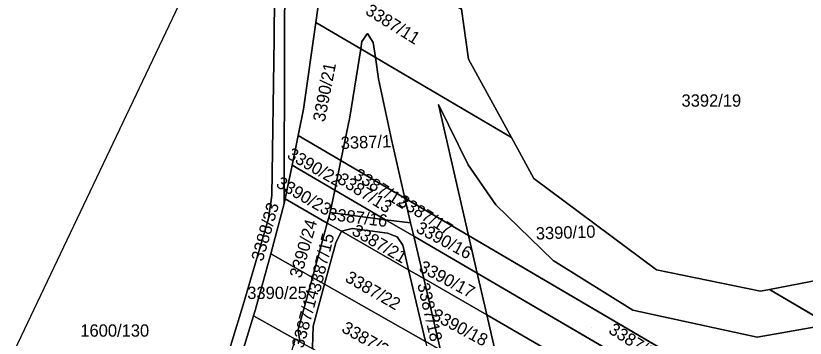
# Model space of a CAD drawing. Extents: x -262715 to -259381, y -1237238 to -1231182.
# Drawn here: x -261658.5 to -261530.6, y -1236768.1 to -1236715.8 of the extents above; entities that cross this region are included whole.
import ezdxf

# ---------------------------------------------------------------- set-up
doc = ezdxf.new("R2010")
doc.units = 0
for name, color, linetype in [('body_kn', 7, 'Continuous'), ('kladpar_druhypozemkov', 7, 'Continuous'), ('kladpar_hranice', 7, 'Continuous'), ('kladpar_parcelnecisla', 7, 'Continuous'), ('kladpar_plochy', 7, 'Continuous'), ('kladpar_sipky', 7, 'Continuous')]:
    doc.layers.add(name, color=color, linetype=linetype)

msp = doc.modelspace()

# ---------------------------------------------------------------- linework, layer by layer
at = {"layer": 'body_kn'}
for p, q in [((-261609.91, -1236716.84), (-261609.91, -1236716.84)), ((-261609.91, -1236716.84), (-261609.91, -1236716.84)), ((-261601.5, -1236718.66), (-261601.5, -1236718.66)), ((-261616.66, -1236719.48), (-261616.66, -1236719.48)), ((-261614.95, -1236719.59), (-261614.95, -1236719.59)), ((-261602.42, -1236719.93), (-261602.42, -1236719.93)), ((-261600.59, -1236720.1), (-261600.59, -1236720.1)), ((-261602.61, -1236721.14), (-261602.61, -1236721.14)), ((-261602.61, -1236721.14), (-261602.61, -1236721.14)), ((-261600.23, -1236722.54), (-261600.23, -1236722.54)), ((-261585.14, -1236722.79), (-261585.14, -1236722.79)), ((-261599.71, -1236726.01), (-261599.71, -1236726.01)), ((-261590, -1236730.13), (-261590, -1236730.13)), ((-261611.87, -1236730.89), (-261611.87, -1236730.89)), ((-261604.37, -1236732.22), (-261604.37, -1236732.22)), ((-261612.74, -1236735.16), (-261612.74, -1236735.16)), ((-261612.74, -1236735.16), (-261612.74, -1236735.16)), ((-261597.63, -1236735.85), (-261597.63, -1236735.85)), ((-261578.19, -1236735.52), (-261578.19, -1236735.52)), ((-261578.19, -1236735.52), (-261578.19, -1236735.52)), ((-261605.82, -1236739.23), (-261605.82, -1236739.23)), ((-261605.82, -1236739.23), (-261605.82, -1236739.23)), ((-261613.73, -1236740), (-261613.73, -1236740)), ((-261613.73, -1236740), (-261613.73, -1236740)), ((-261585.18, -1236739.92), (-261585.18, -1236739.92)), ((-261574.56, -1236742.18), (-261574.56, -1236742.18)), ((-261606.82, -1236744.04), (-261606.82, -1236744.04)), ((-261606.82, -1236744.04), (-261606.82, -1236744.04)), ((-261617.01, -1236744.91), (-261617.01, -1236744.91)), ((-261614.85, -1236745.47), (-261614.85, -1236745.47)), ((-261614.85, -1236745.47), (-261614.85, -1236745.47)), ((-261595.45, -1236745.32), (-261595.45, -1236745.32)), ((-261595.45, -1236745.32), (-261595.45, -1236745.32)), ((-261615, -1236746.23), (-261615, -1236746.23)), ((-261580.74, -1236746.42), (-261580.74, -1236746.42)), ((-261607.58, -1236747.69), (-261607.58, -1236747.69)), ((-261607.58, -1236747.69), (-261607.58, -1236747.69)), ((-261617.53, -1236748.67), (-261617.53, -1236748.67)), ((-261608.04, -1236749.39), (-261608.04, -1236749.39)), ((-261608.04, -1236749.39), (-261608.04, -1236749.39)), ((-261598.59, -1236748.85), (-261598.59, -1236748.85)), ((-261598.59, -1236748.85), (-261598.59, -1236748.85)), ((-261594.52, -1236749.37), (-261594.52, -1236749.37)), ((-261605.73, -1236750.68), (-261605.73, -1236750.68)), ((-261605.73, -1236750.68), (-261605.73, -1236750.68)), ((-261603.98, -1236750.28), (-261603.98, -1236750.28)), ((-261598.28, -1236751.01), (-261598.28, -1236751.01)), ((-261596.72, -1236751.59), (-261596.72, -1236751.59)), ((-261594.01, -1236751.52), (-261594.01, -1236751.52)), ((-261594.01, -1236751.52), (-261594.01, -1236751.52)), ((-261585.13, -1236751.39), (-261585.13, -1236751.39)), ((-261585.13, -1236751.39), (-261585.13, -1236751.39)), ((-261606.66, -1236752.6), (-261606.66, -1236752.6)), ((-261595.81, -1236752.95), (-261595.81, -1236752.95)), ((-261617.2, -1236754.37), (-261617.2, -1236754.37)), ((-261617.2, -1236754.37), (-261617.2, -1236754.37)), ((-261571.43, -1236755.44), (-261571.43, -1236755.44)), ((-261594.86, -1236756.98), (-261594.86, -1236756.98)), ((-261594.86, -1236756.98), (-261594.86, -1236756.98)), ((-261583.73, -1236757.53), (-261583.73, -1236757.53)), ((-261583.73, -1236757.53), (-261583.73, -1236757.53)), ((-261554.67, -1236756.97), (-261554.67, -1236756.97)), ((-261610.45, -1236758.21), (-261610.45, -1236758.21)), ((-261610.45, -1236758.21), (-261610.45, -1236758.21)), ((-261592.4, -1236758.4), (-261592.4, -1236758.4)), ((-261592.4, -1236758.4), (-261592.4, -1236758.4)), ((-261608.49, -1236759.32), (-261608.49, -1236759.32)), ((-261608.49, -1236759.32), (-261608.49, -1236759.32)), ((-261536.36, -1236760.16), (-261536.36, -1236760.16)), ((-261536.36, -1236760.16), (-261536.36, -1236760.16)), ((-261537.81, -1236760.44), (-261537.81, -1236760.44)), ((-261621.67, -1236762.66), (-261621.67, -1236762.66)), ((-261619.69, -1236763.54), (-261619.69, -1236763.54)), ((-261558.51, -1236763.51), (-261558.51, -1236763.51)), ((-261619.97, -1236764.44), (-261619.97, -1236764.44)), ((-261619.97, -1236764.44), (-261619.97, -1236764.44)), ((-261582.18, -1236764.28), (-261582.18, -1236764.28)), ((-261582.18, -1236764.28), (-261582.18, -1236764.28)), ((-261610.33, -1236766.1), (-261610.33, -1236766.1)), ((-261612.74, -1236766.62), (-261612.74, -1236766.62)), ((-261538.34, -1236767.9), (-261538.34, -1236767.9))]:
    msp.add_line(p, q, dxfattribs=at)
at = {"layer": 'kladpar_druhypozemkov'}
for p, q in [((-261601.43, -1236721.27), (-261601.43, -1236721.27)), ((-261609.78, -1236726.54), (-261609.78, -1236726.54)), ((-261545.72, -1236728.04), (-261545.72, -1236728.04)), ((-261601.45, -1236734.83), (-261601.45, -1236734.83)), ((-261609.61, -1236739.69), (-261609.61, -1236739.69)), ((-261604.85, -1236741.85), (-261604.85, -1236741.85)), ((-261615.92, -1236743.88), (-261615.92, -1236743.88)), ((-261610.5, -1236744.77), (-261610.5, -1236744.77)), ((-261604.29, -1236747.74), (-261604.29, -1236747.74)), ((-261595.5, -1236750.62), (-261595.5, -1236750.62)), ((-261569.59, -1236750.25), (-261569.59, -1236750.25)), ((-261612.88, -1236752.22), (-261612.88, -1236752.22)), ((-261607.4, -1236751.83), (-261607.4, -1236751.83)), ((-261588.52, -1236751.75), (-261588.52, -1236751.75)), ((-261598.18, -1236752.66), (-261598.18, -1236752.66)), ((-261594.55, -1236754.58), (-261594.55, -1236754.58)), ((-261587.96, -1236758.17), (-261587.96, -1236758.17)), ((-261614.96, -1236759.73), (-261614.96, -1236759.73)), ((-261599.79, -1236760.04), (-261599.79, -1236760.04)), ((-261593.52, -1236760), (-261593.52, -1236760)), ((-261609.86, -1236760.62), (-261609.86, -1236760.62)), ((-261642.3, -1236765.79), (-261642.3, -1236765.79)), ((-261585.91, -1236766.13), (-261585.91, -1236766.13)), ((-261565.16, -1236766.37), (-261565.16, -1236766.37)), ((-261600.61, -1236767.77), (-261600.61, -1236767.77))]:
    msp.add_line(p, q, dxfattribs=at)
at = {"layer": 'kladpar_hranice'}
for p, q in [((-261609.91, -1236716.84), (-261602.61, -1236721.14)), ((-261602.61, -1236721.14), (-261609.91, -1236716.84)), ((-261600.23, -1236722.54), (-261602.61, -1236721.14)), ((-261602.61, -1236721.14), (-261600.23, -1236722.54)), ((-261600.23, -1236722.54), (-261578.19, -1236735.52)), ((-261578.19, -1236735.52), (-261600.23, -1236722.54)), ((-261613.73, -1236740), (-261612.74, -1236735.16)), ((-261605.82, -1236739.23), (-261612.74, -1236735.16)), ((-261612.74, -1236735.16), (-261605.82, -1236739.23)), ((-261605.82, -1236739.23), (-261606.82, -1236744.04)), ((-261606.82, -1236744.04), (-261605.82, -1236739.23)), ((-261595.45, -1236745.32), (-261605.82, -1236739.23)), ((-261605.82, -1236739.23), (-261595.45, -1236745.32)), ((-261614.85, -1236745.47), (-261613.73, -1236740)), ((-261606.82, -1236744.04), (-261613.73, -1236740)), ((-261613.73, -1236740), (-261606.82, -1236744.04)), ((-261598.59, -1236748.85), (-261606.82, -1236744.04)), ((-261606.82, -1236744.04), (-261598.59, -1236748.85)), ((-261608.04, -1236749.39), (-261614.85, -1236745.47)), ((-261614.85, -1236745.47), (-261608.04, -1236749.39)), ((-261585.13, -1236751.39), (-261595.45, -1236745.32)), ((-261595.45, -1236745.32), (-261585.13, -1236751.39)), ((-261608.04, -1236749.39), (-261607.58, -1236747.69)), ((-261607.58, -1236747.69), (-261598.59, -1236748.85)), ((-261608.04, -1236749.39), (-261610.45, -1236758.21)), ((-261610.45, -1236758.21), (-261608.04, -1236749.39)), ((-261605.73, -1236750.68), (-261608.04, -1236749.39)), ((-261608.04, -1236749.39), (-261605.73, -1236750.68)), ((-261594.01, -1236751.52), (-261598.59, -1236748.85)), ((-261598.59, -1236748.85), (-261594.01, -1236751.52)), ((-261594.86, -1236756.98), (-261605.73, -1236750.68)), ((-261605.73, -1236750.68), (-261594.86, -1236756.98)), ((-261594.01, -1236751.52), (-261592.4, -1236758.4)), ((-261583.73, -1236757.53), (-261594.01, -1236751.52)), ((-261594.01, -1236751.52), (-261583.73, -1236757.53)), ((-261592.4, -1236758.4), (-261594.01, -1236751.52)), ((-261585.13, -1236751.39), (-261583.73, -1236757.53)), ((-261530.9, -1236783.26), (-261585.13, -1236751.39)), ((-261585.13, -1236751.39), (-261530.9, -1236783.26)), ((-261583.73, -1236757.53), (-261585.13, -1236751.39)), ((-261610.45, -1236758.21), (-261617.2, -1236754.37)), ((-261617.2, -1236754.37), (-261610.45, -1236758.21)), ((-261592.4, -1236758.4), (-261594.86, -1236756.98)), ((-261594.86, -1236756.98), (-261592.4, -1236758.4)), ((-261592.13, -1236768.61), (-261594.86, -1236756.98)), ((-261594.86, -1236756.98), (-261592.13, -1236768.61)), ((-261583.73, -1236757.53), (-261582.18, -1236764.28)), ((-261534.18, -1236786.46), (-261583.73, -1236757.53)), ((-261583.73, -1236757.53), (-261534.18, -1236786.46)), ((-261582.18, -1236764.28), (-261583.73, -1236757.53)), ((-261608.49, -1236759.32), (-261610.45, -1236758.21)), ((-261610.45, -1236758.21), (-261608.49, -1236759.32)), ((-261592.4, -1236758.4), (-261589.66, -1236770.02)), ((-261582.18, -1236764.28), (-261592.4, -1236758.4)), ((-261592.4, -1236758.4), (-261582.18, -1236764.28)), ((-261589.66, -1236770.02), (-261592.4, -1236758.4)), ((-261592.13, -1236768.61), (-261608.49, -1236759.32)), ((-261608.49, -1236759.32), (-261592.13, -1236768.61)), ((-261526.69, -1236765.86), (-261536.36, -1236760.16)), ((-261536.36, -1236760.16), (-261526.69, -1236765.86)), ((-261622.41, -1236772.37), (-261619.97, -1236764.44)), ((-261582.18, -1236764.28), (-261579.55, -1236775.76)), ((-261537.7, -1236789.9), (-261582.18, -1236764.28)), ((-261582.18, -1236764.28), (-261537.7, -1236789.9)), ((-261579.55, -1236775.76), (-261582.18, -1236764.28))]:
    msp.add_line(p, q, dxfattribs=at)
for points in [[(-261616.37, -1236683.27), (-261616.42, -1236691.04), (-261616.66, -1236719.48), (-261617.01, -1236744.91), (-261617.53, -1236748.67), (-261621.67, -1236762.66), (-261624.31, -1236771.3), (-261627.23, -1236780.87), (-261630.43, -1236791.34), (-261634.96, -1236806.19)], [(-261624.31, -1236771.3), (-261621.67, -1236762.66), (-261617.53, -1236748.67), (-261617.01, -1236744.91), (-261616.66, -1236719.48), (-261616.42, -1236691.04), (-261616.37, -1236683.27)], [(-261614.76, -1236684.18), (-261614.82, -1236690.96), (-261614.95, -1236719.59), (-261615, -1236746.23), (-261617.2, -1236754.37), (-261619.69, -1236763.54), (-261619.97, -1236764.44), (-261622.41, -1236772.37)], [(-261607.13, -1236688.46), (-261607.25, -1236692.87), (-261608.42, -1236704.48), (-261609.04, -1236710.59), (-261609.91, -1236716.84), (-261611.87, -1236730.89), (-261612.74, -1236735.16), (-261613.73, -1236740), (-261614.85, -1236745.47), (-261615, -1236746.23), (-261614.95, -1236719.59), (-261614.82, -1236690.96), (-261614.76, -1236684.18)], [(-261667.29, -1236787.99), (-261622.98, -1236694.82), (-261628.21, -1236689.57)], [(-261484.37, -1236727.9), (-261487.9, -1236731.62), (-261493.75, -1236737.79), (-261502.57, -1236747.11), (-261503.69, -1236748.29), (-261516.11, -1236755.43), (-261518.22, -1236756.65), (-261536.36, -1236760.16), (-261537.81, -1236760.44), (-261554.67, -1236756.97), (-261574.56, -1236742.18), (-261578.19, -1236735.52), (-261585.14, -1236722.79), (-261586.26, -1236714.69), (-261587.48, -1236705.78), (-261587.78, -1236703.62), (-261587.85, -1236699.27)], [(-261609.91, -1236716.84), (-261609.04, -1236710.59), (-261608.42, -1236704.48)], [(-261586.26, -1236714.69), (-261585.14, -1236722.79), (-261578.19, -1236735.52)], [(-261612.74, -1236735.16), (-261611.87, -1236730.89), (-261609.91, -1236716.84)], [(-261602.61, -1236721.14), (-261602.42, -1236719.93), (-261601.5, -1236718.66), (-261600.59, -1236720.1), (-261600.23, -1236722.54)], [(-261600.23, -1236722.54), (-261600.59, -1236720.1), (-261601.5, -1236718.66), (-261602.42, -1236719.93), (-261602.61, -1236721.14)], [(-261602.61, -1236721.14), (-261604.37, -1236732.22), (-261605.82, -1236739.23)], [(-261605.82, -1236739.23), (-261604.37, -1236732.22), (-261602.61, -1236721.14)], [(-261595.45, -1236745.32), (-261597.63, -1236735.85), (-261599.71, -1236726.01), (-261600.23, -1236722.54)], [(-261600.23, -1236722.54), (-261599.71, -1236726.01), (-261597.63, -1236735.85), (-261595.45, -1236745.32)], [(-261526.69, -1236765.86), (-261538.34, -1236767.9), (-261558.51, -1236763.51), (-261571.43, -1236755.44), (-261580.74, -1236746.42), (-261585.18, -1236739.92), (-261590, -1236730.13), (-261585.13, -1236751.39)], [(-261585.13, -1236751.39), (-261590, -1236730.13), (-261585.18, -1236739.92), (-261580.74, -1236746.42), (-261571.43, -1236755.44), (-261558.51, -1236763.51), (-261538.34, -1236767.9), (-261526.69, -1236765.86)], [(-261578.19, -1236735.52), (-261574.56, -1236742.18), (-261554.67, -1236756.97), (-261537.81, -1236760.44), (-261536.36, -1236760.16)], [(-261606.82, -1236744.04), (-261607.58, -1236747.69), (-261608.04, -1236749.39)], [(-261598.59, -1236748.85), (-261607.58, -1236747.69), (-261606.82, -1236744.04)], [(-261617.2, -1236754.37), (-261615, -1236746.23), (-261614.85, -1236745.47)], [(-261595.45, -1236745.32), (-261594.52, -1236749.37), (-261598.59, -1236748.85)], [(-261594.01, -1236751.52), (-261594.52, -1236749.37), (-261595.45, -1236745.32)], [(-261598.59, -1236748.85), (-261594.52, -1236749.37), (-261594.01, -1236751.52)], [(-261605.73, -1236750.68), (-261606.66, -1236752.6), (-261608.49, -1236759.32)], [(-261608.49, -1236759.32), (-261606.66, -1236752.6), (-261605.73, -1236750.68)], [(-261594.86, -1236756.98), (-261595.81, -1236752.95), (-261596.72, -1236751.59), (-261598.28, -1236751.01), (-261603.98, -1236750.28), (-261605.73, -1236750.68)], [(-261605.73, -1236750.68), (-261603.98, -1236750.28), (-261598.28, -1236751.01), (-261596.72, -1236751.59), (-261595.81, -1236752.95), (-261594.86, -1236756.98)], [(-261619.97, -1236764.44), (-261619.69, -1236763.54), (-261617.2, -1236754.37)], [(-261536.36, -1236760.16), (-261518.22, -1236756.65), (-261516.11, -1236755.43)], [(-261610.45, -1236758.21), (-261612.74, -1236766.62), (-261612.46, -1236768.65)], [(-261612.46, -1236768.65), (-261612.74, -1236766.62), (-261610.45, -1236758.21)], [(-261608.49, -1236759.32), (-261610.33, -1236766.1), (-261610.43, -1236769.54), (-261610.33, -1236769.84)], [(-261610.33, -1236769.84), (-261610.43, -1236769.54), (-261610.33, -1236766.1), (-261608.49, -1236759.32)], [(-261619.97, -1236764.44), (-261613.23, -1236768.22), (-261615.65, -1236776.18), (-261622.41, -1236772.37)], [(-261612.46, -1236768.65), (-261613.23, -1236768.22), (-261619.97, -1236764.44)]]:
    msp.add_lwpolyline(points, dxfattribs=at)
at = {"layer": 'kladpar_plochy'}
for points in [[(-261634.96, -1236806.19), (-261667.29, -1236787.99), (-261622.98, -1236694.82), (-261628.21, -1236689.57), (-261616.27, -1236667.16), (-261616.32, -1236674.75), (-261619.69, -1236681.41), (-261616.37, -1236683.27), (-261616.42, -1236691.04), (-261616.66, -1236719.48), (-261617.01, -1236744.91), (-261617.53, -1236748.67), (-261621.67, -1236762.66), (-261624.31, -1236771.3), (-261627.23, -1236780.87), (-261630.43, -1236791.34)], [(-261484.37, -1236727.9), (-261487.9, -1236731.62), (-261493.75, -1236737.79), (-261502.57, -1236747.11), (-261503.69, -1236748.29), (-261516.11, -1236755.43), (-261518.22, -1236756.65), (-261536.36, -1236760.16), (-261537.81, -1236760.44), (-261554.67, -1236756.97), (-261574.56, -1236742.18), (-261578.19, -1236735.52), (-261585.14, -1236722.79), (-261586.26, -1236714.69), (-261587.48, -1236705.78), (-261587.78, -1236703.62), (-261587.85, -1236699.27), (-261578.96, -1236704.26), (-261576.72, -1236690.83), (-261588.03, -1236684.42), (-261587.66, -1236669.96), (-261570.28, -1236679.67), (-261530.91, -1236701.65), (-261515.83, -1236710.16)], [(-261622.41, -1236772.37), (-261624.31, -1236771.3), (-261621.67, -1236762.66), (-261617.53, -1236748.67), (-261617.01, -1236744.91), (-261616.66, -1236719.48), (-261616.42, -1236691.04), (-261616.37, -1236683.27), (-261614.76, -1236684.18), (-261614.82, -1236690.96), (-261614.95, -1236719.59), (-261615, -1236746.23), (-261617.2, -1236754.37), (-261619.69, -1236763.54), (-261619.97, -1236764.44)], [(-261614.76, -1236684.18), (-261607.13, -1236688.46), (-261607.25, -1236692.87), (-261608.42, -1236704.48), (-261609.04, -1236710.59), (-261609.91, -1236716.84), (-261611.87, -1236730.89), (-261612.74, -1236735.16), (-261613.73, -1236740), (-261614.85, -1236745.47), (-261615, -1236746.23), (-261614.95, -1236719.59), (-261614.82, -1236690.96)], [(-261608.42, -1236704.48), (-261603.29, -1236704.8), (-261586.26, -1236714.69), (-261585.14, -1236722.79), (-261578.19, -1236735.52), (-261600.23, -1236722.54), (-261600.59, -1236720.1), (-261601.5, -1236718.66), (-261602.42, -1236719.93), (-261602.61, -1236721.14), (-261609.91, -1236716.84), (-261609.04, -1236710.59)], [(-261609.91, -1236716.84), (-261602.61, -1236721.14), (-261604.37, -1236732.22), (-261605.82, -1236739.23), (-261612.74, -1236735.16), (-261611.87, -1236730.89)], [(-261602.61, -1236721.14), (-261602.42, -1236719.93), (-261601.5, -1236718.66), (-261600.59, -1236720.1), (-261600.23, -1236722.54)], [(-261602.61, -1236721.14), (-261600.23, -1236722.54), (-261599.71, -1236726.01), (-261597.63, -1236735.85), (-261595.45, -1236745.32), (-261605.82, -1236739.23), (-261604.37, -1236732.22)], [(-261536.36, -1236760.16), (-261526.69, -1236765.86), (-261538.34, -1236767.9), (-261558.51, -1236763.51), (-261571.43, -1236755.44), (-261580.74, -1236746.42), (-261585.18, -1236739.92), (-261590, -1236730.13), (-261585.13, -1236751.39), (-261595.45, -1236745.32), (-261597.63, -1236735.85), (-261599.71, -1236726.01), (-261600.23, -1236722.54), (-261578.19, -1236735.52), (-261574.56, -1236742.18), (-261554.67, -1236756.97), (-261537.81, -1236760.44)], [(-261526.69, -1236765.86), (-261518.23, -1236770.84), (-261519.57, -1236772.19), (-261530.9, -1236783.26), (-261585.13, -1236751.39), (-261590, -1236730.13), (-261585.18, -1236739.92), (-261580.74, -1236746.42), (-261571.43, -1236755.44), (-261558.51, -1236763.51), (-261538.34, -1236767.9)], [(-261612.74, -1236735.16), (-261605.82, -1236739.23), (-261606.82, -1236744.04), (-261613.73, -1236740)], [(-261605.82, -1236739.23), (-261595.45, -1236745.32), (-261594.52, -1236749.37), (-261598.59, -1236748.85), (-261606.82, -1236744.04)], [(-261613.73, -1236740), (-261606.82, -1236744.04), (-261607.58, -1236747.69), (-261608.04, -1236749.39), (-261614.85, -1236745.47)], [(-261606.82, -1236744.04), (-261598.59, -1236748.85), (-261607.58, -1236747.69)], [(-261614.85, -1236745.47), (-261608.04, -1236749.39), (-261610.45, -1236758.21), (-261617.2, -1236754.37), (-261615, -1236746.23)], [(-261595.45, -1236745.32), (-261585.13, -1236751.39), (-261583.73, -1236757.53), (-261594.01, -1236751.52), (-261594.52, -1236749.37)], [(-261607.58, -1236747.69), (-261598.59, -1236748.85), (-261594.01, -1236751.52), (-261592.4, -1236758.4), (-261594.86, -1236756.98), (-261595.81, -1236752.95), (-261596.72, -1236751.59), (-261598.28, -1236751.01), (-261603.98, -1236750.28), (-261605.73, -1236750.68), (-261608.04, -1236749.39)], [(-261608.04, -1236749.39), (-261605.73, -1236750.68), (-261606.66, -1236752.6), (-261608.49, -1236759.32), (-261610.45, -1236758.21)], [(-261598.59, -1236748.85), (-261594.52, -1236749.37), (-261594.01, -1236751.52)], [(-261605.73, -1236750.68), (-261594.86, -1236756.98), (-261592.13, -1236768.61), (-261608.49, -1236759.32), (-261606.66, -1236752.6)], [(-261605.73, -1236750.68), (-261603.98, -1236750.28), (-261598.28, -1236751.01), (-261596.72, -1236751.59), (-261595.81, -1236752.95), (-261594.86, -1236756.98)], [(-261594.01, -1236751.52), (-261583.73, -1236757.53), (-261582.18, -1236764.28), (-261592.4, -1236758.4)], [(-261585.13, -1236751.39), (-261530.9, -1236783.26), (-261534.18, -1236786.46), (-261583.73, -1236757.53)], [(-261617.2, -1236754.37), (-261610.45, -1236758.21), (-261612.74, -1236766.62), (-261612.46, -1236768.65), (-261613.23, -1236768.22), (-261619.97, -1236764.44), (-261619.69, -1236763.54)], [(-261516.11, -1236755.43), (-261509.65, -1236759.19), (-261516.6, -1236764.09), (-261526.69, -1236765.86), (-261536.36, -1236760.16), (-261518.22, -1236756.65)], [(-261594.86, -1236756.98), (-261592.4, -1236758.4), (-261589.66, -1236770.02), (-261592.13, -1236768.61)], [(-261583.73, -1236757.53), (-261534.18, -1236786.46), (-261537.7, -1236789.9), (-261582.18, -1236764.28)], [(-261610.45, -1236758.21), (-261608.49, -1236759.32), (-261610.33, -1236766.1), (-261610.43, -1236769.54), (-261610.33, -1236769.84), (-261612.46, -1236768.65), (-261612.74, -1236766.62)], [(-261592.4, -1236758.4), (-261582.18, -1236764.28), (-261579.55, -1236775.76), (-261589.66, -1236770.02)], [(-261608.49, -1236759.32), (-261592.13, -1236768.61), (-261589.05, -1236781.76), (-261610.33, -1236769.84), (-261610.43, -1236769.54), (-261610.33, -1236766.1)], [(-261619.97, -1236764.44), (-261613.23, -1236768.22), (-261615.65, -1236776.18), (-261622.41, -1236772.37)], [(-261582.18, -1236764.28), (-261537.7, -1236789.9), (-261543.94, -1236796), (-261579.55, -1236775.76)]]:
    msp.add_lwpolyline(points, close=True, dxfattribs=at)
at = {"layer": 'kladpar_sipky'}
for p, q in [((-261601.53, -1236720.12), (-261601.53, -1236720.12)), ((-261606.35, -1236746.28), (-261606.35, -1236746.28)), ((-261595.28, -1236749.94), (-261595.28, -1236749.94))]:
    msp.add_line(p, q, dxfattribs=at)

# ---------------------------------------------------------------- texts
at = {"layer": 'kladpar_parcelnecisla'}
for s, rotation, p in [('3387/11', 328, (-261602.01, -1236715.39)), ('3390/21', 79, (-261608.44, -1236733.07)), ('3387/1', 2, (-261605.82, -1236737.38)), ('3390/22', 330, (-261614.7, -1236738.76)), ('3387/12', 328, (-261603.95, -1236742.06)), ('3390/23', 330, (-261616.48, -1236743.42)), ('3387/13', 328, (-261606.56, -1236742.75)), ('3387/17', 328, (-261596.72, -1236746.34)), ('3388/33', 74, (-261618.49, -1236755.7)), ('3387/16', 353, (-261608.01, -1236748.85)), ('3390/24', 74, (-261612.29, -1236758.44)), ('3387/21', 330, (-261604.22, -1236751.16)), ('3390/16', 332, (-261593.81, -1236750.78)), ('3390/10', 2, (-261574.2, -1236752.07)), ('3387/15', 76, (-261609.21, -1236760.72)), ('3390/17', 332, (-261593.34, -1236757.1)), ('3387/22', 330, (-261605.29, -1236758.75)), ('3390/25', 360, (-261621, -1236761.7)), ('3387/18', 283, (-261593.45, -1236759.33)), ('3387/14', 75, (-261611.91, -1236769.78)), ('3390/18', 332, (-261591.23, -1236764.9)), ('3387/2', 330, (-261605.86, -1236766.93)), ('3387/26', 328, (-261562.59, -1236767.14))]:
    msp.add_text(s, height=2, rotation=rotation, dxfattribs=at).set_placement(p)
for s, p in [('3392/19', (-261550.62, -1236730.51)), ('1600/130', (-261648.05, -1236767.81))]:
    msp.add_text(s, height=2, dxfattribs=at).set_placement(p)

doc.saveas('drawing.dxf')
